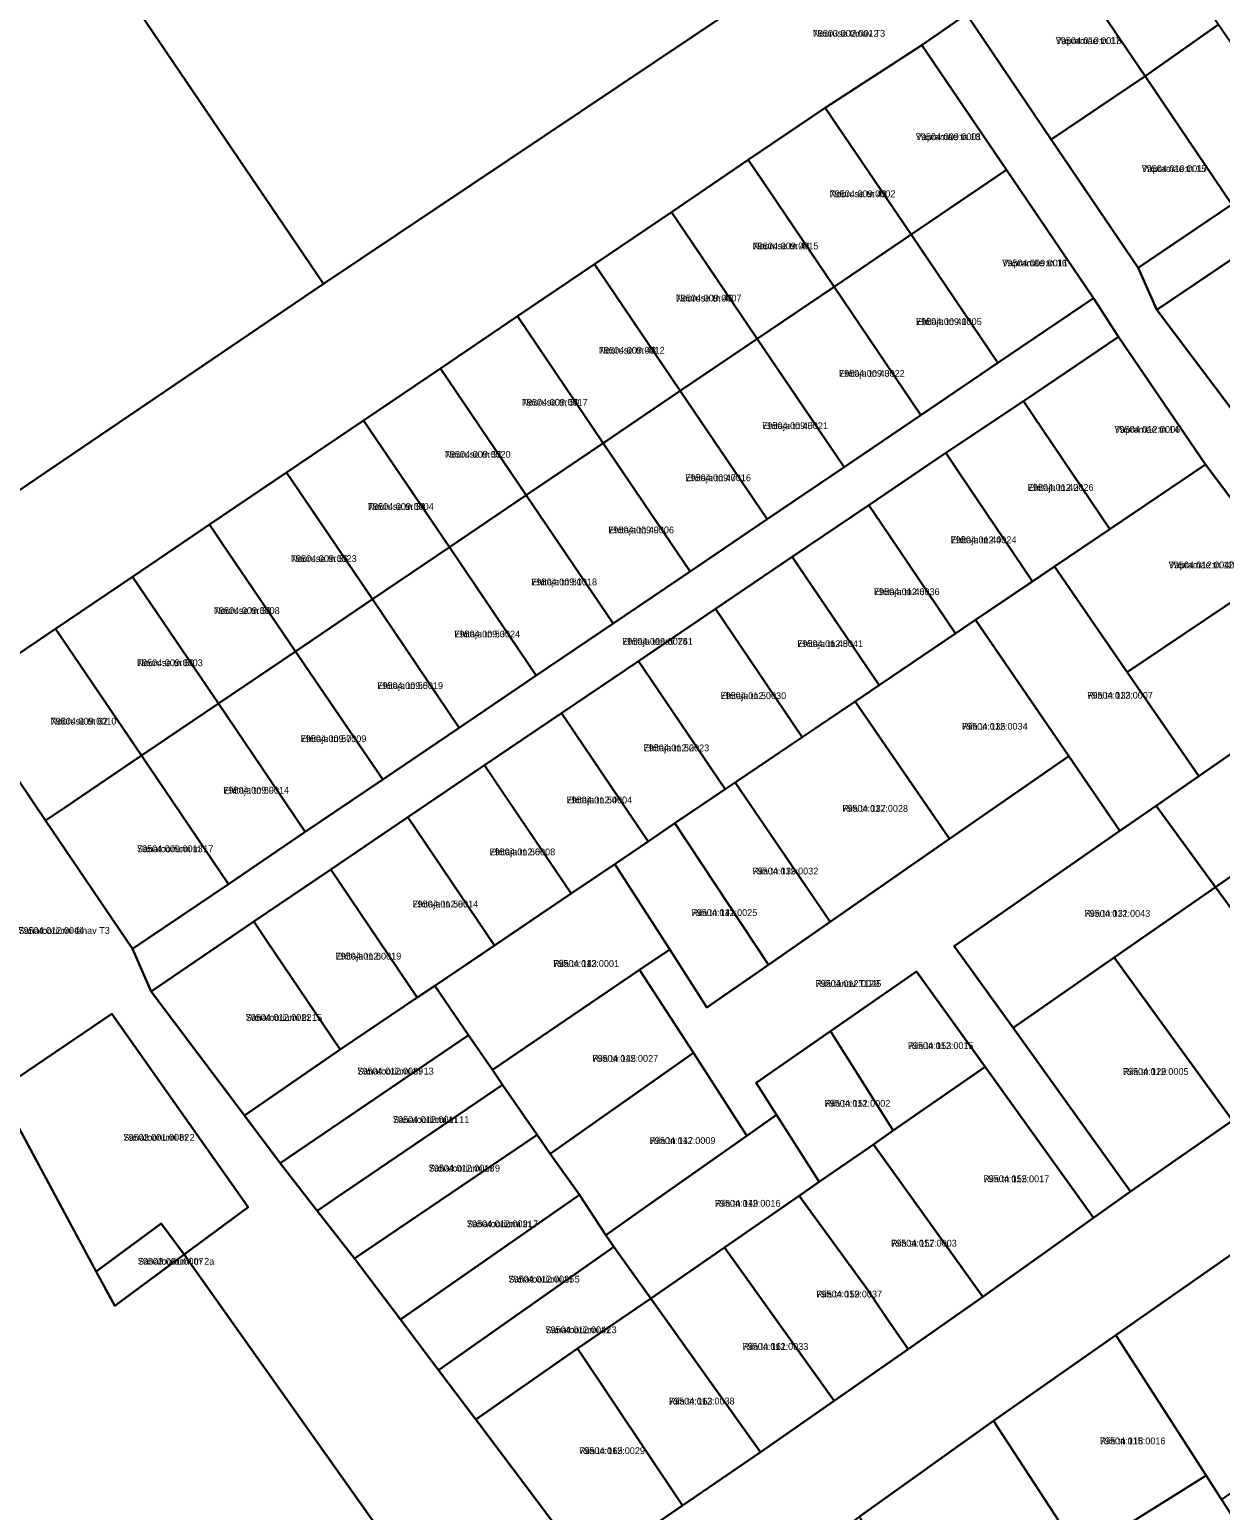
# Model space of a CAD drawing. Extents: x 643847 to 663718, y 6468443 to 6482775.
# Drawn here: x 657333 to 657595.7, y 6472196.8 to 6472523.3 of the extents above; entities that cross this region are included whole.
import ezdxf

# ---------------------------------------------------------------- set-up
doc = ezdxf.new("R2010")
doc.units = 0
for name, color, linetype in [('L_AADRESS', 7, 'Continuous'), ('PIIR', 7, 'Continuous'), ('TUNNUS', 7, 'Continuous')]:
    doc.layers.add(name, color=color, linetype=linetype)

msp = doc.modelspace()

# ---------------------------------------------------------------- linework, layer by layer
at = {"layer": 'PIIR'}
for points in [[(657766.14, 6472598.47), (657772.39, 6472590.41), (657752.81, 6472577.35), (657736.29, 6472566.15), (657719.72, 6472554.93), (657703.12, 6472543.7), (657686.43, 6472532.4), (657670.02, 6472521.3), (657653.46, 6472510.1), (657636.64, 6472498.72), (657620.37, 6472487.71), (657603.83, 6472476.51), (657581.69, 6472461.52), (657577.55, 6472470.79), (657598.23, 6472484.79), (657614.78, 6472495.99), (657647.88, 6472518.4), (657664.28, 6472529.51), (657680.97, 6472540.81), (657697.48, 6472551.99), (657714.03, 6472563.19), (657730.57, 6472574.39), (657747.12, 6472585.59)], [(657495.32, 6472532.63), (657397.83, 6472467.29), (657345.9, 6472543.87), (657363.28, 6472555.66), (657354.3, 6472568.92), (657391.69, 6472593.48), (657411.77, 6472565.12), (657408.99, 6472548.84)], [(657397.83, 6472467.29), (657283.18, 6472389.54), (657231.32, 6472484.94), (657235.57, 6472487.84), (657336.92, 6472557.13), (657345.9, 6472543.87)], [(657576.7, 6472552.27), (657595.27, 6472524.43), (657579.06, 6472513.1), (657560.13, 6472541.05)], [(657539.64, 6472526.77), (657560.13, 6472541.05), (657579.06, 6472513.1), (657558.37, 6472499.11)], [(657648.79, 6472372.49), (657675.72, 6472336.75), (657665.75, 6472329.95), (657639.17, 6472365.28), (657625.83, 6472383), (657609.48, 6472404.73), (657592.38, 6472427.44), (657573.17, 6472455.58), (657567.65, 6472464.1), (657548.47, 6472492.4), (657529.83, 6472519.93), (657539.64, 6472526.77), (657558.37, 6472499.11), (657577.55, 6472470.79), (657581.69, 6472461.52), (657602.32, 6472434.16), (657618.91, 6472412.13), (657635.45, 6472390.19)], [(657598.23, 6472484.79), (657579.06, 6472513.1), (657595.27, 6472524.43), (657614.78, 6472495.99)], [(657548.47, 6472492.4), (657527.44, 6472478.14), (657508.51, 6472506.09), (657529.83, 6472519.93)], [(657558.37, 6472499.11), (657579.06, 6472513.1), (657598.23, 6472484.79), (657577.55, 6472470.79)], [(657508.51, 6472506.09), (657527.44, 6472478.14), (657510.47, 6472466.65), (657494.35, 6472490.46), (657491.54, 6472494.6)], [(657491.54, 6472494.6), (657494.35, 6472490.46), (657510.47, 6472466.65), (657493.5, 6472455.15), (657477.38, 6472478.97), (657474.57, 6472483.1)], [(657567.65, 6472464.1), (657546.61, 6472449.83), (657527.44, 6472478.14), (657548.47, 6472492.4)], [(657423.22, 6472227.74), (657431.43, 6472216.83), (657456.36, 6472183.73), (657442.57, 6472169.24), (657431.16, 6472162.91), (657367.08, 6472253.27), (657381.26, 6472263.64), (657351.15, 6472306.33), (657326.17, 6472289.42), (657223.76, 6472479.25), (657231.32, 6472484.94), (657283.18, 6472389.54), (657317.63, 6472376.92), (657336.56, 6472348.96), (657355.74, 6472320.65), (657359.82, 6472311.25), (657380.39, 6472283.88), (657388.29, 6472273.35), (657396.45, 6472262.9), (657404.67, 6472252.36), (657414.82, 6472238.88)], [(657474.57, 6472483.1), (657477.38, 6472478.97), (657493.5, 6472455.15), (657476.53, 6472443.66), (657460.41, 6472467.47), (657457.6, 6472471.61)], [(657367.08, 6472253.27), (657431.16, 6472162.91), (657271.19, 6472186.88), (657108.55, 6472162.43), (657060.49, 6472399.17), (657051.34, 6472444.25), (657223.76, 6472479.25), (657326.17, 6472289.42), (657347.72, 6472249.45), (657351.8, 6472241.9)], [(657529.61, 6472438.31), (657510.47, 6472466.65), (657527.44, 6472478.14), (657546.61, 6472449.83)], [(657581.69, 6472461.52), (657603.83, 6472476.51), (657623.01, 6472448.16), (657606.46, 6472436.97), (657602.32, 6472434.16)], [(657457.6, 6472471.61), (657460.41, 6472467.47), (657476.53, 6472443.66), (657459.56, 6472432.17), (657440.64, 6472460.13)], [(657567.65, 6472464.1), (657573.17, 6472455.58), (657552.24, 6472441.42), (657535.08, 6472429.98), (657518.11, 6472418.49), (657501.23, 6472407.06), (657484.31, 6472395.6), (657467.34, 6472384.1), (657450.37, 6472372.6), (657433.38, 6472361.11), (657416.43, 6472349.64), (657399.43, 6472338.13), (657382.46, 6472326.66), (657359.82, 6472311.25), (657355.74, 6472320.65), (657376.86, 6472334.93), (657393.81, 6472346.41), (657410.92, 6472357.98), (657427.79, 6472369.4), (657444.77, 6472380.88), (657461.74, 6472392.37), (657478.73, 6472403.86), (657495.7, 6472415.35), (657512.68, 6472426.85), (657529.61, 6472438.31), (657546.61, 6472449.83)], [(657512.68, 6472426.85), (657493.5, 6472455.15), (657510.47, 6472466.65), (657529.61, 6472438.31)], [(657440.64, 6472460.13), (657459.56, 6472432.17), (657442.58, 6472420.69), (657423.66, 6472448.64)], [(657476.53, 6472443.66), (657493.5, 6472455.15), (657512.68, 6472426.85), (657495.7, 6472415.35)], [(657592.38, 6472427.44), (657571.29, 6472413.18), (657552.24, 6472441.42), (657573.17, 6472455.58)], [(657423.66, 6472448.64), (657442.58, 6472420.69), (657425.61, 6472409.2), (657406.67, 6472437.15)], [(657478.73, 6472403.86), (657459.56, 6472432.17), (657476.53, 6472443.66), (657495.7, 6472415.35)], [(657552.24, 6472441.42), (657571.29, 6472413.18), (657559.06, 6472404.92), (657554.25, 6472401.66), (657537.89, 6472425.84), (657535.08, 6472429.98)], [(657406.67, 6472437.15), (657425.61, 6472409.2), (657408.62, 6472397.71), (657389.7, 6472425.67)], [(657461.74, 6472392.37), (657442.58, 6472420.69), (657459.56, 6472432.17), (657478.73, 6472403.86)], [(657535.08, 6472429.98), (657537.89, 6472425.84), (657554.25, 6472401.66), (657541.66, 6472393.15), (657537.27, 6472390.18), (657520.91, 6472414.35), (657518.11, 6472418.49)], [(657389.7, 6472425.67), (657408.62, 6472397.71), (657391.64, 6472386.22), (657375.52, 6472410.03), (657372.72, 6472414.19)], [(657609.48, 6472404.73), (657575.13, 6472381.64), (657559.06, 6472404.92), (657571.29, 6472413.18), (657592.38, 6472427.44)], [(657444.77, 6472380.88), (657425.61, 6472409.2), (657442.58, 6472420.69), (657461.74, 6472392.37)], [(657518.11, 6472418.49), (657520.91, 6472414.35), (657537.27, 6472390.18), (657520.39, 6472378.77), (657501.23, 6472407.06)], [(657372.72, 6472414.19), (657375.52, 6472410.03), (657391.64, 6472386.22), (657374.67, 6472374.74), (657355.74, 6472402.69)], [(657427.79, 6472369.4), (657408.62, 6472397.71), (657425.61, 6472409.2), (657444.77, 6472380.88)], [(657501.23, 6472407.06), (657520.39, 6472378.77), (657515.13, 6472375.19), (657503.46, 6472367.31), (657484.31, 6472395.6)], [(657355.74, 6472402.69), (657374.67, 6472374.74), (657357.69, 6472363.25), (657338.76, 6472391.2)], [(657541.66, 6472393.15), (657559.06, 6472404.92), (657575.13, 6472381.64), (657590.93, 6472358.75), (657581.49, 6472352.19), (657573.5, 6472346.64), (657562.21, 6472363.13)], [(657625.83, 6472383), (657590.93, 6472358.75), (657575.13, 6472381.64), (657609.48, 6472404.73)], [(657410.92, 6472357.98), (657391.64, 6472386.22), (657408.62, 6472397.71), (657427.79, 6472369.4)], [(657484.31, 6472395.6), (657503.46, 6472367.31), (657488.63, 6472357.29), (657486.47, 6472355.83), (657470.14, 6472379.96), (657467.34, 6472384.1)], [(657535.92, 6472344.87), (657515.13, 6472375.19), (657520.39, 6472378.77), (657537.27, 6472390.18), (657541.66, 6472393.15), (657562.21, 6472363.13)], [(657338.76, 6472391.2), (657357.69, 6472363.25), (657340.7, 6472351.76), (657336.56, 6472348.96), (657317.63, 6472376.92)], [(657393.81, 6472346.41), (657374.67, 6472374.74), (657391.64, 6472386.22), (657410.92, 6472357.98)], [(657467.34, 6472384.1), (657470.14, 6472379.96), (657486.47, 6472355.83), (657475.36, 6472348.32), (657469.48, 6472344.34), (657453.16, 6472368.46), (657450.37, 6472372.6)], [(657639.17, 6472365.28), (657616.92, 6472349.79), (657594.61, 6472334.26), (657581.49, 6472352.19), (657590.93, 6472358.75), (657625.83, 6472383)], [(657376.86, 6472334.93), (657357.69, 6472363.25), (657374.67, 6472374.74), (657393.81, 6472346.41)], [(657450.37, 6472372.6), (657453.16, 6472368.46), (657469.48, 6472344.34), (657462.08, 6472339.33), (657452.48, 6472332.86), (657436.18, 6472356.97), (657433.38, 6472361.11)], [(657535.92, 6472344.87), (657509.59, 6472326.58), (657488.63, 6472357.29), (657515.13, 6472375.19)], [(657376.86, 6472334.93), (657355.74, 6472320.65), (657336.56, 6472348.96), (657340.7, 6472351.76), (657357.69, 6472363.25)], [(657575.88, 6472267.1), (657567.7, 6472261.36), (657543.78, 6472294.6), (657528.66, 6472315.63), (657509.67, 6472302.48), (657493.25, 6472291.11), (657497.78, 6472284.01), (657491.23, 6472279.41), (657479.42, 6472297.69), (657467.58, 6472316.01), (657474.21, 6472320.5), (657482.43, 6472307.71), (657495.98, 6472317.12), (657509.59, 6472326.58), (657535.92, 6472344.87), (657562.21, 6472363.13), (657573.5, 6472346.64), (657536.97, 6472321.25), (657549.94, 6472303.2)], [(657433.38, 6472361.11), (657452.48, 6472332.86), (657435.54, 6472321.39), (657416.43, 6472349.64)], [(657495.98, 6472317.12), (657475.36, 6472348.32), (657486.47, 6472355.83), (657488.63, 6472357.29), (657509.59, 6472326.58)], [(657549.94, 6472303.2), (657536.97, 6472321.25), (657573.5, 6472346.64), (657581.49, 6472352.19), (657594.61, 6472334.26), (657572.28, 6472318.74)], [(657620.84, 6472298.54), (657594.61, 6472334.26), (657616.92, 6472349.79), (657643.3, 6472314.25)], [(657416.43, 6472349.64), (657435.54, 6472321.39), (657422.38, 6472312.48), (657418.52, 6472309.92), (657399.43, 6472338.13)], [(657482.43, 6472307.71), (657474.21, 6472320.5), (657462.08, 6472339.33), (657469.48, 6472344.34), (657475.36, 6472348.32), (657495.98, 6472317.12)], [(657399.43, 6472338.13), (657418.52, 6472309.92), (657401.53, 6472298.43), (657385.26, 6472322.51), (657382.46, 6472326.66)], [(657474.21, 6472320.5), (657467.58, 6472316.01), (657435.1, 6472293.97), (657430.96, 6472299.98), (657422.38, 6472312.48), (657452.48, 6472332.86), (657462.08, 6472339.33)], [(657598.36, 6472282.82), (657596.6, 6472285.24), (657572.28, 6472318.74), (657594.61, 6472334.26), (657620.84, 6472298.54)], [(657359.82, 6472311.25), (657382.46, 6472326.66), (657385.26, 6472322.51), (657401.53, 6472298.43), (657380.39, 6472283.88)], [(657575.88, 6472267.1), (657549.94, 6472303.2), (657572.28, 6472318.74), (657596.6, 6472285.24), (657598.36, 6472282.82)], [(657458.76, 6472283.13), (657447.86, 6472275.44), (657444.94, 6472279.63), (657437.36, 6472290.67), (657435.1, 6472293.97), (657467.58, 6472316.01), (657479.42, 6472297.69)], [(657523.49, 6472280.55), (657509.67, 6472302.48), (657528.66, 6472315.63), (657543.78, 6472294.6)], [(657380.39, 6472283.88), (657401.53, 6472298.43), (657418.52, 6472309.92), (657422.38, 6472312.48), (657429.86, 6472301.58), (657388.29, 6472273.35)], [(657381.26, 6472263.64), (657367.08, 6472253.27), (657362.01, 6472260.09), (657347.72, 6472249.46), (657326.17, 6472289.42), (657351.15, 6472306.33)], [(657388.29, 6472273.35), (657429.86, 6472301.58), (657435.1, 6472293.97), (657437.36, 6472290.67), (657400.39, 6472265.57), (657396.45, 6472262.9)], [(657519.13, 6472277.53), (657507.2, 6472269.27), (657497.78, 6472284.01), (657493.25, 6472291.11), (657509.67, 6472302.48), (657523.49, 6472280.55)], [(657491.23, 6472279.41), (657468.97, 6472263.73), (657460.14, 6472257.52), (657454.3, 6472266.37), (657447.86, 6472275.44), (657458.76, 6472283.13), (657479.42, 6472297.69)], [(657543.31, 6472243.93), (657519.13, 6472277.53), (657523.49, 6472280.55), (657543.78, 6472294.6), (657567.7, 6472261.36)], [(657404.67, 6472252.36), (657396.45, 6472262.9), (657400.39, 6472265.57), (657437.36, 6472290.67), (657444.94, 6472279.63)], [(657497.78, 6472284.01), (657507.2, 6472269.27), (657502.74, 6472266.19), (657486.29, 6472254.8), (657470.03, 6472243.55), (657461.91, 6472254.94), (657460.14, 6472257.52), (657468.97, 6472263.73), (657491.23, 6472279.41)], [(657404.67, 6472252.36), (657444.94, 6472279.63), (657447.86, 6472275.44), (657454.3, 6472266.37), (657414.82, 6472238.88)], [(657526.79, 6472232.37), (657522.21, 6472239.03), (657517.59, 6472245.81), (657502.74, 6472266.19), (657507.2, 6472269.27), (657519.13, 6472277.53), (657543.31, 6472243.93)], [(657414.82, 6472238.88), (657454.3, 6472266.37), (657460.14, 6472257.52), (657461.91, 6472254.94), (657423.22, 6472227.74)], [(657510.52, 6472220.99), (657486.29, 6472254.8), (657502.74, 6472266.19), (657517.59, 6472245.81), (657522.21, 6472239.03), (657526.79, 6472232.37)], [(657367.08, 6472253.27), (657351.8, 6472241.9), (657347.72, 6472249.46), (657362.01, 6472260.09)], [(657423.22, 6472227.74), (657461.91, 6472254.94), (657470.03, 6472243.55), (657453.84, 6472232.53), (657431.43, 6472216.83)], [(657494.24, 6472209.62), (657470.03, 6472243.55), (657486.29, 6472254.8), (657510.52, 6472220.99)], [(657598.95, 6472253.83), (657619.45, 6472221.61), (657622.08, 6472217.55), (657595.92, 6472199.19), (657592.52, 6472204.48), (657572.64, 6472235.43)], [(657477.06, 6472197.88), (657453.84, 6472232.53), (657470.03, 6472243.55), (657494.24, 6472209.62)], [(657456.36, 6472183.73), (657431.43, 6472216.83), (657453.84, 6472232.53), (657477.06, 6472197.88)], [(657545.61, 6472216.53), (657572.64, 6472235.43), (657592.52, 6472204.48), (657564.8, 6472187.18)], [(657545.61, 6472216.53), (657564.8, 6472187.18), (657569.18, 6472180.48), (657540.83, 6472160.52), (657516.03, 6472195.42)], [(657564.8, 6472187.18), (657592.52, 6472204.48), (657595.92, 6472199.19), (657608.61, 6472179.42), (657582.03, 6472160.81), (657569.18, 6472180.48)]]:
    msp.add_lwpolyline(points, close=True, dxfattribs=at)
for points in [[(657283.18, 6472389.54), (657397.83, 6472467.29), (657495.32, 6472532.63)], [(657539.64, 6472526.77), (657529.83, 6472519.93), (657508.51, 6472506.09), (657491.54, 6472494.6), (657474.57, 6472483.1), (657457.6, 6472471.61), (657440.64, 6472460.13), (657423.66, 6472448.64), (657406.67, 6472437.15), (657389.7, 6472425.67), (657372.72, 6472414.19), (657355.74, 6472402.69), (657338.76, 6472391.2), (657317.63, 6472376.92)], [(657598.95, 6472253.83), (657572.64, 6472235.43), (657545.61, 6472216.53), (657516.03, 6472195.42), (657484.98, 6472173.27), (657467.71, 6472157.28), (657455.37, 6472144.29), (657417.35, 6472149.89), (657431.16, 6472162.91), (657442.57, 6472169.24), (657456.36, 6472183.73), (657477.06, 6472197.88), (657494.24, 6472209.62), (657510.52, 6472220.99), (657526.79, 6472232.37), (657543.31, 6472243.93), (657567.7, 6472261.36), (657575.88, 6472267.1), (657598.36, 6472282.82)]]:
    msp.add_lwpolyline(points, dxfattribs=at)

# ---------------------------------------------------------------- texts
at = {"layer": 'L_AADRESS'}
for s, p in [('Nooruse tänav T3', (657505.78, 6472521.76)), ('Vapramäe tn 17', (657559.35, 6472520.14)), ('Vapramäe tn 18', (657528.49, 6472498.96)), ('Vapramäe tn 15', (657578.3, 6472491.94)), ('Nooruse tn 42', (657509.49, 6472486.37)), ('Nooruse tn 44', (657492.52, 6472474.88)), ('Vapramäe tn 16', (657547.54, 6472471.12)), ('Nooruse tn 46', (657475.55, 6472463.38)), ('Ehitaja tn 41', (657528.54, 6472458.2)), ('Nooruse tn 48', (657458.59, 6472451.88)), ('Ehitaja tn 43', (657511.55, 6472446.78)), ('Nooruse tn 50', (657441.61, 6472440.41)), ('Ehitaja tn 45', (657494.61, 6472435.24)), ('Vapramäe tn 14', (657572.31, 6472434.43)), ('Nooruse tn 52', (657424.62, 6472428.93)), ('Ehitaja tn 47', (657477.63, 6472423.76)), ('Ehitaja tn 42', (657553.18, 6472421.63)), ('Nooruse tn 54', (657407.66, 6472417.42)), ('Ehitaja tn 49', (657460.65, 6472412.26)), ('Ehitaja tn 44', (657536.18, 6472410.07)), ('Nooruse tn 56', (657390.67, 6472405.94)), ('Vapramäe tn 12', (657584.26, 6472404.54)), ('Ehitaja tn 51', (657443.68, 6472400.79)), ('Ehitaja tn 46', (657519.25, 6472398.63)), ('Nooruse tn 58', (657373.69, 6472394.47)), ('Ehitaja tn 53', (657426.7, 6472389.31)), ('Ehitaja tänav T41', (657463.71, 6472387.68)), ('Ehitaja tn 48', (657502.35, 6472387.18)), ('Nooruse tn 60', (657356.71, 6472382.97)), ('Ehitaja tn 55', (657409.71, 6472377.92)), ('Ehitaja tn 50', (657485.4, 6472375.7)), ('Riia tn 133', (657566.29, 6472375.8)), ('Nooruse tn 62', (657337.66, 6472370.08)), ('Riia tn 135', (657538.67, 6472368.95)), ('Ehitaja tn 57', (657392.8, 6472366.22)), ('Ehitaja tn 52', (657468.42, 6472364.2)), ('Ehitaja tn 59', (657375.75, 6472354.86)), ('Ehitaja tn 54', (657451.43, 6472352.72)), ('Riia tn 137', (657512.28, 6472350.85)), ('Sanatooriumi tn 17', (657356.71, 6472341.95)), ('Ehitaja tn 56', (657434.45, 6472341.26)), ('Riia tn 139', (657492.48, 6472337.04)), ('Ehitaja tn 58', (657417.48, 6472329.76)), ('Riia tn 141', (657479.03, 6472327.88)), ('Riia tn 131', (657565.7, 6472327.7)), ('Sanatooriumi tänav T3', (657330.54, 6472323.93)), ('Ehitaja tn 60', (657400.49, 6472318.27)), ('Riia tn 143', (657448.53, 6472316.65)), ('Riia tänav T129', (657506.37, 6472312.24)), ('Sanatooriumi tn 15', (657380.68, 6472304.76)), ('Riia tn 153', (657526.73, 6472298.54)), ('Sanatooriumi tn 13', (657405.31, 6472292.92)), ('Riia tn 145', (657457.16, 6472295.73)), ('Riia tn 129', (657574.15, 6472292.84)), ('Riia tn 151', (657508.37, 6472285.83)), ('Sanatooriumi tn 11', (657413.16, 6472282.24)), ('Sanatooriumi tn 2', (657353.71, 6472278.31)), ('Riia tn 147', (657469.8, 6472277.61)), ('Sanatooriumi tn 9', (657421.05, 6472271.52)), ('Riia tn 155', (657543.42, 6472269.18)), ('Riia tn 149', (657484.15, 6472263.78)), ('Sanatooriumi tn 7', (657429.47, 6472259.25)), ('Riia tn 157', (657523.03, 6472254.98)), ('Sanatooriumi tn 2a', (657356.9, 6472250.99)), ('Sanatooriumi tn 5', (657438.63, 6472247.05)), ('Riia tn 159', (657506.54, 6472243.76)), ('Sanatooriumi tn 3', (657446.79, 6472235.88)), ('Riia tn 161', (657490.28, 6472232.21)), ('Riia tn 163', (657474.04, 6472220.16)), ('Riia tn 118', (657569.07, 6472211.39)), ('Riia tn 165', (657454.25, 6472209.23))]:
    msp.add_text(s, height=1.5, dxfattribs=at).set_placement(p)
at = {"layer": 'TUNNUS'}
for s, p in [('79503:002:0012', (657505.78, 6472521.76)), ('79504:010:0018', (657559.35, 6472520.14)), ('79504:009:0001', (657528.49, 6472498.96)), ('79504:010:0017', (657578.3, 6472491.94)), ('79504:009:0002', (657509.49, 6472486.37)), ('79504:009:0015', (657492.52, 6472474.88)), ('79504:009:0011', (657547.54, 6472471.12)), ('79504:009:0007', (657475.55, 6472463.38)), ('79504:009:0005', (657528.54, 6472458.2)), ('79504:009:0012', (657458.59, 6472451.88)), ('79504:009:0022', (657511.55, 6472446.78)), ('79504:009:0017', (657441.61, 6472440.41)), ('79504:009:0021', (657494.61, 6472435.24)), ('79504:012:0006', (657572.31, 6472434.43)), ('79504:009:0020', (657424.62, 6472428.93)), ('79504:009:0016', (657477.63, 6472423.76)), ('79504:012:0026', (657553.18, 6472421.63)), ('79504:009:0004', (657407.66, 6472417.42)), ('79504:009:0006', (657460.65, 6472412.26)), ('79504:012:0024', (657536.18, 6472410.07)), ('79504:009:0023', (657390.67, 6472405.94)), ('79504:012:0040', (657584.26, 6472404.54)), ('79504:009:0018', (657443.68, 6472400.79)), ('79504:012:0036', (657519.25, 6472398.63)), ('79504:009:0008', (657373.69, 6472394.47)), ('79504:009:0024', (657426.7, 6472389.31)), ('79504:009:0025', (657463.71, 6472387.68)), ('79504:012:0041', (657502.35, 6472387.18)), ('79504:009:0003', (657356.71, 6472382.97)), ('79504:009:0019', (657409.71, 6472377.92)), ('79504:012:0030', (657485.4, 6472375.7)), ('79504:012:0007', (657566.29, 6472375.8)), ('79504:009:0010', (657337.66, 6472370.08)), ('79504:012:0034', (657538.67, 6472368.95)), ('79504:009:0009', (657392.8, 6472366.22)), ('79504:012:0023', (657468.42, 6472364.2)), ('79504:009:0014', (657375.75, 6472354.86)), ('79504:012:0004', (657451.43, 6472352.72)), ('79504:012:0028', (657512.28, 6472350.85)), ('79504:009:0013', (657356.71, 6472341.95)), ('79504:012:0008', (657434.45, 6472341.26)), ('79504:012:0032', (657492.48, 6472337.04)), ('79504:012:0014', (657417.48, 6472329.76)), ('79504:012:0025', (657479.03, 6472327.88)), ('79504:012:0043', (657565.7, 6472327.7)), ('79504:012:0044', (657330.54, 6472323.93)), ('79504:012:0019', (657400.49, 6472318.27)), ('79504:012:0001', (657448.53, 6472316.65)), ('79504:012:0045', (657506.37, 6472312.24)), ('79504:012:0022', (657380.68, 6472304.76)), ('79504:012:0015', (657526.73, 6472298.54)), ('79504:012:0039', (657405.31, 6472292.92)), ('79504:012:0027', (657457.16, 6472295.73)), ('79504:012:0005', (657574.15, 6472292.84)), ('79504:012:0002', (657508.37, 6472285.83)), ('79504:012:0011', (657413.16, 6472282.24)), ('79503:001:0082', (657353.71, 6472278.31)), ('79504:012:0009', (657469.8, 6472277.61)), ('79504:012:0018', (657421.05, 6472271.52)), ('79504:012:0017', (657543.42, 6472269.18)), ('79504:012:0016', (657484.15, 6472263.78)), ('79504:012:0021', (657429.47, 6472259.25)), ('79504:012:0003', (657523.03, 6472254.98)), ('79503:001:0007', (657356.9, 6472250.99)), ('79504:012:0035', (657438.63, 6472247.05)), ('79504:012:0037', (657506.54, 6472243.76)), ('79504:012:0042', (657446.79, 6472235.88)), ('79504:012:0033', (657490.28, 6472232.21)), ('79504:012:0038', (657474.04, 6472220.16)), ('79504:015:0016', (657569.07, 6472211.39)), ('79504:012:0029', (657454.25, 6472209.23))]:
    msp.add_text(s, height=1.5, dxfattribs=at).set_placement(p)

doc.saveas('drawing.dxf')
